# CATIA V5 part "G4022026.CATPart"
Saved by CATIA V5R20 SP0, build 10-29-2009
Part number: G4022026
Revision: 6
Definition: design
Nomenclature: G4022026
Source: made
Description: NOT SPECIFIED
Bounding box of the stored display mesh (mm): x -15 to 26, y -16 to 16, z -16 to 16
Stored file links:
  C:\Users\Raffaele\Desktop\3D X SITO CF\BOLEX\26-BUSH REF 402\G4022026.CATPart
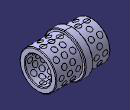
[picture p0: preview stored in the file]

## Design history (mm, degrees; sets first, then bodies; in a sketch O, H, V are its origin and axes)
Body1 "MANIFOLD_SOLID_BREP #9383" (main body)
  Solid1: solid without history
Body2 "MANIFOLD_SOLID_BREP #9532"
  Solid2: solid without history
Body3 "MANIFOLD_SOLID_BREP #9681"
  Solid3: solid without history
Body4 "MANIFOLD_SOLID_BREP #9830"
  Solid4: solid without history
Body5 "MANIFOLD_SOLID_BREP #9979"
  Solid5: solid without history
Body6 "MANIFOLD_SOLID_BREP #10128"
  Solid6: solid without history
Body7 "MANIFOLD_SOLID_BREP #10277"
  Solid7: solid without history
Body8 "MANIFOLD_SOLID_BREP #10426"
  Solid8: solid without history
Body9 "MANIFOLD_SOLID_BREP #10575"
  Solid9: solid without history
Body10 "MANIFOLD_SOLID_BREP #10724"
  Solid10: solid without history
Body11 "MANIFOLD_SOLID_BREP #10873"
  Solid11: solid without history
Body12 "MANIFOLD_SOLID_BREP #11022"
  Solid12: solid without history
Body13 "MANIFOLD_SOLID_BREP #11171"
  Solid13: solid without history
Body14 "MANIFOLD_SOLID_BREP #11320"
  Solid14: solid without history
Body15 "MANIFOLD_SOLID_BREP #11469"
  Solid15: solid without history
Body16 "MANIFOLD_SOLID_BREP #11618"
  Solid16: solid without history
Body17 "MANIFOLD_SOLID_BREP #11767"
  Solid17: solid without history
Body18 "MANIFOLD_SOLID_BREP #11916"
  Solid18: solid without history
Body19 "MANIFOLD_SOLID_BREP #12065"
  Solid19: solid without history
Body20 "MANIFOLD_SOLID_BREP #12214"
  Solid20: solid without history
Body21 "MANIFOLD_SOLID_BREP #12363"
  Solid21: solid without history
Body22 "MANIFOLD_SOLID_BREP #12512"
  Solid22: solid without history
Body23 "MANIFOLD_SOLID_BREP #12661"
  Solid23: solid without history
Body24 "MANIFOLD_SOLID_BREP #12810"
  Solid24: solid without history
Body25 "MANIFOLD_SOLID_BREP #12959"
  Solid25: solid without history
Body26 "MANIFOLD_SOLID_BREP #13108"
  Solid26: solid without history
Body27 "MANIFOLD_SOLID_BREP #13257"
  Solid27: solid without history
Body28 "MANIFOLD_SOLID_BREP #13406"
  Solid28: solid without history
Body29 "MANIFOLD_SOLID_BREP #13555"
  Solid29: solid without history
Body30 "MANIFOLD_SOLID_BREP #13704"
  Solid30: solid without history
Body31 "MANIFOLD_SOLID_BREP #13853"
  Solid31: solid without history
Body32 "MANIFOLD_SOLID_BREP #14002"
  Solid32: solid without history
Body33 "MANIFOLD_SOLID_BREP #14151"
  Solid33: solid without history
Body34 "MANIFOLD_SOLID_BREP #14300"
  Solid34: solid without history
Body35 "MANIFOLD_SOLID_BREP #14449"
  Solid35: solid without history
Body36 "MANIFOLD_SOLID_BREP #14598"
  Solid36: solid without history
Body37 "MANIFOLD_SOLID_BREP #14747"
  Solid37: solid without history
Body38 "MANIFOLD_SOLID_BREP #14896"
  Solid38: solid without history
Body39 "MANIFOLD_SOLID_BREP #15045"
  Solid39: solid without history
Body40 "MANIFOLD_SOLID_BREP #15194"
  Solid40: solid without history
Body41 "MANIFOLD_SOLID_BREP #15343"
  Solid41: solid without history
Body42 "MANIFOLD_SOLID_BREP #15492"
  Solid42: solid without history
Body43 "MANIFOLD_SOLID_BREP #15641"
  Solid43: solid without history
Body44 "MANIFOLD_SOLID_BREP #15790"
  Solid44: solid without history
Body45 "MANIFOLD_SOLID_BREP #15939"
  Solid45: solid without history
Body46 "MANIFOLD_SOLID_BREP #16088"
  Solid46: solid without history
Body47 "MANIFOLD_SOLID_BREP #16237"
  Solid47: solid without history
Body48 "MANIFOLD_SOLID_BREP #16386"
  Solid48: solid without history
Body49 "MANIFOLD_SOLID_BREP #16535"
  Solid49: solid without history
Body50 "MANIFOLD_SOLID_BREP #16684"
  Solid50: solid without history
Body51 "MANIFOLD_SOLID_BREP #16833"
  Solid51: solid without history
Body52 "MANIFOLD_SOLID_BREP #16982"
  Solid52: solid without history
Body53 "MANIFOLD_SOLID_BREP #17131"
  Solid53: solid without history
Body54 "MANIFOLD_SOLID_BREP #17280"
  Solid54: solid without history
Body55 "MANIFOLD_SOLID_BREP #17429"
  Solid55: solid without history
Body56 "MANIFOLD_SOLID_BREP #17578"
  Solid56: solid without history
Body57 "MANIFOLD_SOLID_BREP #17727"
  Solid57: solid without history
Body58 "MANIFOLD_SOLID_BREP #17876"
  Solid58: solid without history
Body59 "MANIFOLD_SOLID_BREP #18025"
  Solid59: solid without history
Body60 "MANIFOLD_SOLID_BREP #18174"
  Solid60: solid without history
Body61 "MANIFOLD_SOLID_BREP #18323"
  Solid61: solid without history
Body62 "MANIFOLD_SOLID_BREP #18472"
  Solid62: solid without history
Body63 "MANIFOLD_SOLID_BREP #18621"
  Solid63: solid without history
Body64 "MANIFOLD_SOLID_BREP #18770"
  Solid64: solid without history
Body65 "MANIFOLD_SOLID_BREP #18919"
  Solid65: solid without history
